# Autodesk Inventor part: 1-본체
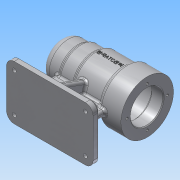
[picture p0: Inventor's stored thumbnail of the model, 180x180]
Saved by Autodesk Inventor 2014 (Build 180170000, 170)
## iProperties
Created: 2016-06
Part Number: 1-본체
Material: 알루미늄 6061
Document SubType Name: Modeling
Designer: 406-8
Density: 2.71 g/cm^3
Appearance: 알루미늄 - 평지
Mass: 673.897 g
Surface Area: 647.223 cm^2
Volume: 248.67 cm^3
Author: 406-8
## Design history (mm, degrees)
sketch "스케치1"
  geometry: L1 (46, 35)-(-46, 35); L2 (-56, 25)-(-56, -25); L3 (-46, -35)-(46, -35); L4 (56, -25)-(56, 25); L5 (56, 35)-(-56, -35); L6 (-56, 35)-(56, -35); A1 r 10 centre (46, -25) between (46, -35) and (56, -25); A2 r 10 centre (-46, -25) between (-56, -25) and (-46, -35); A3 r 10 centre (-46, 25) between (-46, 35) and (-56, 25); A4 r 10 centre (46, 25) between (56, 25) and (46, 35); 1 further point
  constraints: 12 end point, 8 point on circle, 8 point on line, 8 tangent, 4 centre point, 3 equal radius, 2 midpoint, 2 parallel, 1 horizontal, 1 perpendicular
  dimensions: "d0" = 112 distance of L6.end L5.end; "d1" = 70 distance of L5.end L6.start; "d2" = 10 radius of A1
extrude "돌출1" new body sketch "스케치1" distance "d3" = 10; taper "d4" = 0 deg
sketch "스케치2"
  geometry: A1 r 10 centre (-46, 25) between (-46, 35) and (-56, 25) reference; A2 r 10 centre (46, 25) between (56, 25) and (46, 35) reference; A3 r 10 centre (46, -25) between (46, -35) and (56, -25) reference; A4 r 10 centre (-46, -25) between (-56, -25) and (-46, -35) reference; 5 further points
  constraints: 4 coincident
hole "구멍1" sketch "스케치2" at (-46, 25), (46, 25), (46, -25), (-46, -25) diameter "d5" = 5; stored, may be unused: countersink angle "d9" = 90 deg, drill point angle "d11" = 118 deg; dims "d6" = 6, "d7" = 9, "d8" = 4, "d10" = 8
sketch "스케치3"
  geometry: L1 (-56, 70)-(56, 70); L2 (46, 0)-(-46, 0) reference; L3 (-56, 0)-(-56, 10) reference; L4 (56, 0)-(56, 10) reference; L5 (56, 70)-(56, 104); L6 (56, 104)-(28, 104); L7 (28, 104)-(28, 100); L8 (28, 100)-(-11, 100); L9 (-11, 100)-(-11, 97); L10 (-11, 97)-(-31, 97); L11 (-31, 97)-(-31, 95); L12 (-31, 95)-(-56, 95); L13 (-56, 95)-(-56, 70); L14 (56, 91)-(41, 91); L15 (41, 91)-(41, 91); L16 (38, 94)-(-10, 94); L17 (-13, 91)-(-13, 91); L18 (-13, 91)-(-24.7, 91); L19 (-25, 90.7)-(-25, 87.5); L20 (-25, 87.5)-(-42.7, 87.5); L21 (-43, 87.2)-(-43, 86); L22 (-43, 86)-(-46.7, 86); L23 (-47, 85.7)-(-47, 80.5); L24 (-47, 80.5)-(-47, 80.5); L25 (-50, 77.5)-(-50, 70); A1 r 3 centre (-47, 77.5) between (-47, 80.5) and (-50, 77.5); A2 r 0.3 centre (-46.7, 85.7) between (-46.7, 86) and (-47, 85.7); A3 r 0.3 centre (-42.7, 87.2) between (-42.7, 87.5) and (-43, 87.2); A4 r 0.3 centre (-24.7, 90.7) between (-24.7, 91) and (-25, 90.7); A5 r 3 centre (-10, 91) between (-10, 94) and (-13, 91); A6 r 3 centre (38, 91) between (41, 91) and (38, 94); 7 further points
  constraints: 44 end point, 16 parallel, 14 point on line, 12 point on circle, 12 tangent, 6 centre point, 3 equal radius, 3 perpendicular, 2 collinear, 2 vertical alignment, 1 horizontal
  dimensions: "d12" = 70 distance between parallel lines of L2 L1; "d13" = 68 diameter of L6 L1; "d14" = 60 diameter of L8 L1; "d15" = 54 diameter of L10 L1; "d16" = 50 diameter of L12 L1; "d17" = 25 distance of L11.end L12.end; "d18" = 45 horizontal distance of L9.end L12.end; "d19" = 84 horizontal distance of L7.end L12.end; "d20" = 42 diameter of L14 L1; "d21" = 48 diameter of L16 L1; "d22" = 42 diameter of L18 L1; "d23" = 35 diameter of L20 L1; "d24" = 32 diameter of L22 L1; "d25" = 21 diameter of L24 L1; "d26" = 3 distance of L23.end point (-50, 80.5); "d27" = 4 distance of L21.end point (-47, 86); "d28" = 18 distance of L19.end point (-43, 87.5); "d29" = 12 distance of L17.end point (-25, 91); "d30" = 54 distance of point (41, 94) point (-13, 94); "d31" = 15 distance of L14.start L14.end; "d43" = 3 radius of A1; "d44" = 0.3 radius of A2; "d45" = 3 radius of A5
revolve "회전1" stored, may be unused: angle "d32" = 90 deg
sketch "스케치4"
  geometry: L1 (46, 10)-(-46, 10) reference; L2 (-46, 10)-(-56, 10) reference; L3 (56, 10)-(46, 10) reference; L4 (-36, 10)-(-36, 70); L5 (-36, 70)-(36, 70); L6 (36, 70)-(36, 10); L7 (-56, 0)-(-56, 10) reference; 2 further points
  constraints: 6 end point, 3 perpendicular, 2 point on line, 1 midpoint, 1 vertical alignment
  dimensions: "d33" = 60 distance between parallel lines of L1 L5; "d35" = 20 distance between parallel lines of L4 L7
extrude "돌출2" join sketch "스케치4" stored distance "d36" = 8; taper "d37" = 0 deg
sketch "스케치5"
  geometry: L1 (10, -25)-(10, 25) reference; L2 (10, 28)-(70, 6.162); L3 (70, 6.162)-(70, -6.162); L4 (70, -6.162)-(10, -28); L5 (0, 35)-(10, 35) reference; L6 (10, 25)-(10, 35) reference; L7 (10, -35)-(10, -25) reference; L8 (10, 28)-(10, -28); L9 (10, -35)-(10, -25) reference; L10 (0, -35)-(10, -35) reference; 2 further points
  constraints: 8 end point, 2 point on line, 1 collinear, 1 equal length, 1 horizontal alignment, 1 midpoint, 1 parallel
  dimensions: "d38" = 7 distance from line of L2.start L5; "d39" = 70 distance from line of point (0, 0) L3; "d40" = 110 deg angle of L2 L6; "d68" = 7 vertical distance of L10.start L4.end (derived)
extrude "돌출3" join sketch "스케치5" stored distance "d41" = 8; taper "d42" = 0 deg
revolve "회전2" stored, may be unused: angle "d46" = 90 deg
chamfer "모따기1" distance "d47" = 1; stored, may be unused: second distance "d48" = 2, angle "d49" = 45 deg
chamfer "모따기2" distance "d50" = 4; stored, may be unused: second distance "d51" = 2, angle "d52" = 45 deg
fillet "모깎기1" dims "d53" = 3, "d54" = 10
fillet "모깎기2" dims "d55" = 3
sketch "스케치6"
  geometry: C1 r 34 at (0, 0) reference; A1 r 26 centre (0, 0) between (0, 26) and (26, 0); 3 further points
  constraints: 4 point on circle, 2 horizontal alignment, 2 vertical alignment, 1 centre point, 1 coincident
  dimensions: "d56" = 52 diameter of A1
hole "구멍2" sketch "스케치6" at (0, 26), (26, 0), (0, -26), (-26, 0) diameter "d57" = 3.242; stored, may be unused: countersink angle "d61" = 90 deg, drill point angle "d63" = 118 deg; dims "d58" = 8, "d59" = 9, "d60" = 4, "d62" = 11
sketch "스케치7"
  geometry: L1 (76.657, 104)-(102, 104) reference; L2 (0, 0)-(92, 0) reference; L3 (102, 36)-(102, 104) reference; 2 further points
  constraints: 1 other
  dimensions: "d64" = 70 vertical distance of point (46, 0) point (54, 70); "d65" = 48 distance from line of point (54, 70) L3
feature "엠보싱1" sketch "스케치7" dims "d0" = 112, "d1" = 70, "d2" = 10, "d66" = 0.5, "d67" = 0
node "솔리드1"
